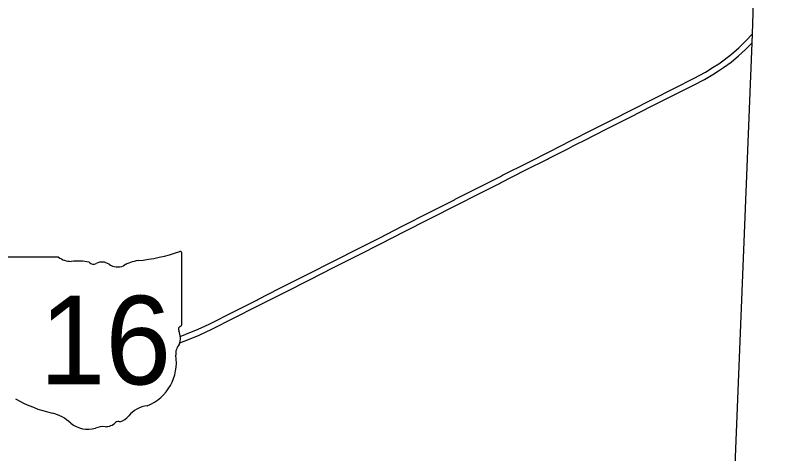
# Model space of a CAD drawing. Extents: x 1853412 to 2125412, y 679418 to 855418.
# Drawn here: x 2045595 to 2055343, y 756444 to 761987 of the extents above; entities that cross this region are included whole.
import ezdxf

# ---------------------------------------------------------------- set-up
doc = ezdxf.new("R2010")
doc.units = 0
for name, color, linetype in [('GM_X_County', 7, 'Continuous'), ('GM_X_State_Shield', 7, 'Continuous'), ('UT_P_Electric', 7, 'Continuous')]:
    doc.layers.add(name, color=color, linetype=linetype)

msp = doc.modelspace()

# ---------------------------------------------------------------- linework, layer by layer
at = {"layer": 'GM_X_County'}
msp.add_lwpolyline([(2055342.8, 773147.1), (2055023.2, 763819.6), (2055000, 763325.7), (2054958.7, 762937.7), (2054917.7, 761752.8), (2054914.8, 761639.3), (2054671.6, 755558.7), (2054400.3, 748991.3), (2054181.7, 742978.3)], dxfattribs=at)
at = {"layer": 'GM_X_State_Shield'}
for p, q in [((2047703.3, 758082.3), (2047703.3, 758972.3)), ((2046140.3, 758930.1), (2045483.9, 758930.1)), ((2047703, 758082.6), (2047703.3, 758082.3))]:
    msp.add_line(p, q, dxfattribs=at)
for centre, radius, start, end in [((2046904.8, 761249.4), 2377, 275.84447, 288.90645), ((2047678.4, 758975.9), 25, 351.86209, 97.738), ((2046296.7, 759127.6), 251.9, 231.61951, 271.11188), ((2046380.2, 757975), 904.2, 80.48669, 94.98827), ((2046585.4, 758913.3), 72.7, 219.79206, 297.10237), ((2046692.1, 758716.6), 151.1, 54.46668, 119.14113), ((2047208, 758410.5), 478.2, 97.34618, 120.76885), ((2046887.1, 758986.3), 181.7, 233.85621, 294.82819), ((2047676.6, 758078.9), 26.7, 289.60381, 7.73413), ((2047697.5, 758017), 38.6, 107.94398, 210.33697), ((2047451.8, 757904.5), 231.8, 340.03296, 23.64957), ((2047792.7, 757709.9), 168.7, 136.8065, 186.92959), ((2047038, 757596.7), 594.5, 292.30889, 8.98584), ((2046442.8, 758629.9), 1716.5, 240.41292, 257.1985), ((2047288.7, 756722), 325.6, 94.40312, 142.57675), ((2045931, 756435.4), 537.1, 47.18416, 75.83597), ((2046876.1, 757034.8), 192.1, 282.87319, 323.27711), ((2046511.9, 757093.1), 340.8, 230.70037, 286.29184), ((2046733.7, 756965.7), 181.6, 268.77702, 315.54927), ((2046897.9, 756800.9), 51.1, 65.75173, 132.64842), ((2046708.8, 756504.9), 280, 85.69512, 111.20995)]:
    msp.add_arc(centre, radius, start, end, dxfattribs=at)
at = {"layer": 'UT_P_Electric'}
msp.add_line((2052656, 760335.6), (2052845, 760431), dxfattribs=at)
for points in [[(2051733.9, 759950.7), (2051762, 759965), (2052084.1, 760128.1), (2052366.8, 760271.6), (2052620.4, 760399.6), (2052904.2, 760542.8), (2053148.1, 760667.6), (2053388.8, 760788.5), (2053653.3, 760922.1), (2053935.6, 761065.6), (2054186.7, 761194.7), (2054329.2, 761270.9), (2054427.9, 761330.6), (2054497, 761375.4), (2054564.4, 761423.7), (2054656.1, 761494.9), (2054751.2, 761577.5), (2054845.3, 761669.4), (2054918.8, 761750)], [(2053264.9, 760643.9), (2053382.7, 760703.7), (2053638.1, 760833.2), (2053923.9, 760977.8), (2054175.5, 761106.1), (2054314.6, 761178.5), (2054420.9, 761240), (2054493.8, 761284.5), (2054556.2, 761326.6), (2054652.5, 761397.5), (2054746, 761474.8), (2054836.5, 761556.8), (2054915.9, 761636.5)], [(2052845, 760431), (2052882.8, 760450.1), (2053132.9, 760576.9), (2053264.9, 760643.9)], [(2052328.4, 760170.1), (2052342.4, 760177.2), (2052594.6, 760304.6), (2052656, 760335.6)], [(2051721.3, 759861.4), (2051735.3, 759868.5), (2052056.6, 760032.8), (2052328.4, 760170.1)], [(2047682.5, 757927), (2047753.3, 757953.3), (2047906.7, 758016.9), (2048047.3, 758082.7), (2048365.4, 758242.1), (2048649.7, 758386.2), (2048663.4, 758393.1), (2048933.5, 758530.5), (2049287.9, 758710.3), (2049638.4, 758888.4), (2049927.5, 759034.8), (2050205.7, 759175.1), (2050492.1, 759319.8), (2050840.3, 759497.9), (2051151.1, 759656.1), (2051161.9, 759661.6), (2051448.6, 759805.7), (2051733.9, 759950.7)], [(2047676, 757845.7), (2047787.6, 757886.4), (2047922.3, 757943.5), (2048079.9, 758016.4), (2048364.8, 758160.2), (2048646, 758302.9), (2049001.5, 758483), (2049326.3, 758647.9), (2049613.9, 758792.5), (2049940.7, 758958.6), (2050225, 759102.5), (2050512, 759247.9), (2050837.1, 759414), (2051193.5, 759595.5), (2051444.5, 759721.5), (2051721.3, 759861.4)]]:
    msp.add_lwpolyline(points, dxfattribs=at)

# ---------------------------------------------------------------- texts
at = {"layer": 'GM_X_State_Shield'}
msp.add_text('16', height=1120.71, dxfattribs=at).set_placement((2045899.9, 757319.6))

doc.saveas('drawing.dxf')
